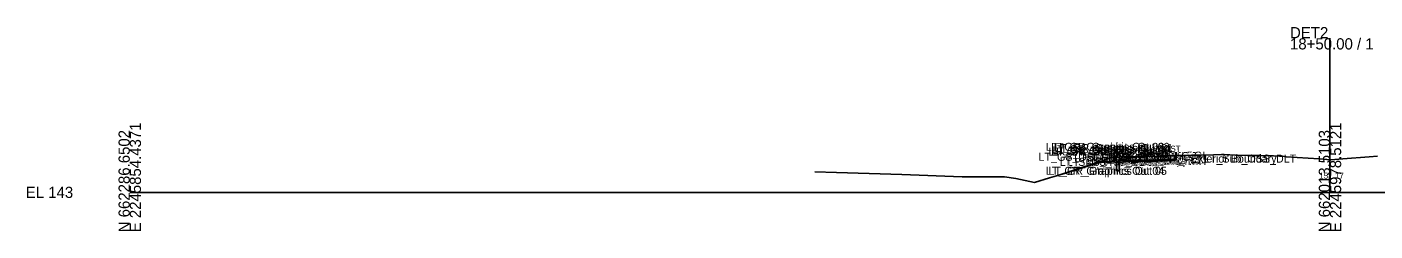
# Model space of a CAD drawing. Extents: x -26 to 603, y -10 to 9526.
# Drawn here: x -25.7 to 311.3, y 1490.3 to 1541.4 of the extents above; entities that cross this region are included whole.
import ezdxf

# ---------------------------------------------------------------- set-up
doc = ezdxf.new("R2010")
doc.units = 0
for name, color, linetype in [('Default', 7, 'Continuous'), ('Exist Cross Section Cell', 7, 'Continuous'), ('Exist XS Center Line Elevation Label', 7, 'Continuous'), ('Exist XS Ground Line', 7, 'Continuous'), ('Prop CMT Guardrail Graphics', 7, 'Continuous'), ('Prop CMT Pvmt Course 1', 7, 'Continuous'), ('Prop CMT Pvmt Course 2', 7, 'Continuous'), ('Prop CMT Pvmt Course 3', 7, 'Continuous'), ('Prop CMT Pvmt Surface', 7, 'Continuous'), ('Prop CMT Pvmt Surface Shoulder', 7, 'Continuous'), ('Prop CMT Shld Paved Course 1', 7, 'Continuous'), ('Prop CMT Shld Paved Course 2', 7, 'Continuous'), ('Prop CMT Shld Paved Course 3', 7, 'Continuous'), ('Prop CMT Slope Grass', 7, 'Continuous'), ('Prop CMT Subgrade Earthwork', 7, 'Continuous'), ('Prop XS SE Text', 7, 'Continuous'), ('Prop XS Side Slope Text', 7, 'Continuous'), ('Scratch_Level_2', 7, 'Continuous')]:
    doc.layers.add(name, color=color, linetype=linetype)

msp = doc.modelspace()

# ---------------------------------------------------------------- linework, layer by layer
at = {"layer": 'Exist Cross Section Cell'}
for p, q in [((300, 1500), (300, 1538.56)), ((0, 1500), (300, 1500)), ((300, 1500), (600, 1500))]:
    msp.add_line(p, q, dxfattribs=at)
at = {"layer": 'Exist XS Ground Line'}
for p, q in [((234.71, 1505.06), (241.84, 1507.32)), ((241.84, 1507.32), (247.92, 1508.19)), ((247.92, 1508.19), (252.23, 1508.88)), ((252.23, 1508.88), (252.65, 1508.89)), ((252.65, 1508.89), (253.46, 1508.92)), ((253.46, 1508.92), (254.75, 1508.96)), ((254.75, 1508.96), (258.62, 1509.11)), ((258.62, 1509.11), (259.31, 1509.2)), ((259.31, 1509.2), (259.85, 1509.19)), ((259.85, 1509.19), (261.29, 1509.19)), ((261.29, 1509.19), (262.49, 1509.23)), ((262.49, 1509.23), (265.41, 1509.28)), ((265.41, 1509.28), (267.33, 1509.31)), ((267.33, 1509.31), (270.91, 1509.36)), ((270.91, 1509.36), (272.92, 1509.44)), ((272.92, 1509.44), (273.57, 1509.49)), ((273.57, 1509.49), (276.4, 1509.3)), ((276.4, 1509.3), (279.42, 1509.24)), ((279.42, 1509.24), (281.12, 1509.21)), ((281.12, 1509.21), (281.89, 1509.19)), ((281.89, 1509.19), (283.67, 1509.16)), ((283.67, 1509.16), (284.44, 1509.19)), ((284.44, 1509.19), (285.91, 1509.15)), ((285.91, 1509.15), (287.38, 1509.09)), ((287.38, 1509.09), (288.15, 1509.07)), ((288.15, 1509.07), (289.04, 1508.88)), ((289.04, 1508.88), (291.81, 1508.72)), ((291.81, 1508.72), (297.3, 1508.4)), ((297.3, 1508.4), (300.23, 1508.15)), ((300.23, 1508.15), (303.23, 1508.38)), ((303.23, 1508.38), (309.76, 1508.87)), ((309.76, 1508.87), (311.89, 1509.04)), ((171.27, 1505.1), (176.66, 1504.94)), ((176.66, 1504.94), (193, 1504.5)), ((193, 1504.5), (208.1, 1503.87)), ((208.1, 1503.87), (218.65, 1503.84)), ((218.65, 1503.84), (221.48, 1503.46)), ((221.48, 1503.46), (226.13, 1502.47)), ((226.13, 1502.47), (229.93, 1503.64)), ((229.93, 1503.64), (231.61, 1504.1)), ((231.61, 1504.1), (234.71, 1505.06))]:
    msp.add_line(p, q, dxfattribs=at)
at = {"layer": 'Prop CMT Guardrail Graphics'}
for points in [[(246.66, 1505.37), (246.66, 1511.37)], [(246.66, 1511.37), (248, 1511.37), (248.27, 1511.08)], [(248.27, 1510.49), (248, 1510.2), (247.33, 1510.2)], [(247.33, 1510.2), (247.33, 1505.37)], [(248.27, 1511.08), (248, 1510.79)], [(248, 1510.79), (248.27, 1510.49)], [(247.33, 1505.37), (246.66, 1505.37)]]:
    msp.add_lwpolyline(points, dxfattribs=at)
at = {"layer": 'Prop CMT Pvmt Course 1'}
for points in [[(261.29, 1509.19), (257.09, 1509.09)], [(257.09, 1509.09), (257.09, 1508.17)], [(257.09, 1508.17), (261.29, 1508.28)], [(261.29, 1508.28), (261.29, 1509.19)]]:
    msp.add_lwpolyline(points, dxfattribs=at)
at = {"layer": 'Prop CMT Pvmt Course 2'}
for points in [[(261.29, 1508.28), (257.09, 1508.17)], [(257.09, 1508.17), (257.09, 1507.84)], [(257.09, 1507.84), (261.29, 1507.94)], [(261.29, 1507.94), (261.29, 1508.28)]]:
    msp.add_lwpolyline(points, dxfattribs=at)
at = {"layer": 'Prop CMT Pvmt Course 3'}
for points in [[(261.29, 1507.94), (257.09, 1507.84)], [(257.09, 1507.84), (261.29, 1507.94)], [(257.09, 1507.84), (257.09, 1507.84)], [(261.29, 1507.94), (261.29, 1507.94)]]:
    msp.add_lwpolyline(points, dxfattribs=at)
at = {"layer": 'Prop CMT Pvmt Surface'}
msp.add_lwpolyline([(261.29, 1509.19), (257.09, 1509.09)], dxfattribs=at)
at = {"layer": 'Prop CMT Pvmt Surface Shoulder'}
msp.add_lwpolyline([(257.09, 1509.09), (248.27, 1508.87)], dxfattribs=at)
at = {"layer": 'Prop CMT Shld Paved Course 1'}
for p, q in [((248.27, 1508.87), (247.33, 1507.93)), ((257.09, 1509.09), (250.03, 1508.91))]:
    msp.add_line(p, q, dxfattribs=at)
for points in [[(249.09, 1507.97), (257.09, 1508.17)], [(257.09, 1508.17), (257.09, 1509.09)]]:
    msp.add_lwpolyline(points, dxfattribs=at)
at = {"layer": 'Prop CMT Shld Paved Course 2'}
for p, q in [((247.33, 1507.93), (247, 1507.6)), ((257.09, 1508.17), (247.33, 1507.93))]:
    msp.add_line(p, q, dxfattribs=at)
for points in [[(248.75, 1507.63), (257.09, 1507.84)], [(257.09, 1507.84), (257.09, 1508.17)]]:
    msp.add_lwpolyline(points, dxfattribs=at)
at = {"layer": 'Prop CMT Shld Paved Course 3'}
for points in [[(257.09, 1507.84), (248.75, 1507.63), (248.25, 1507.62)], [(248.25, 1507.62), (257.09, 1507.84)], [(248.25, 1507.62), (248.25, 1507.62)], [(257.09, 1507.84), (257.09, 1507.84)]]:
    msp.add_lwpolyline(points, dxfattribs=at)
at = {"layer": 'Prop CMT Slope Grass'}
for points in [[(245.27, 1508.63), (232.72, 1504.45)], [(248.27, 1508.87), (245.27, 1508.63)]]:
    msp.add_lwpolyline(points, dxfattribs=at)
at = {"layer": 'Prop CMT Subgrade Earthwork'}
for points in [[(248.25, 1507.62), (241.95, 1507.52)], [(257.09, 1507.84), (248.25, 1507.62)], [(261.29, 1507.94), (257.09, 1507.84)]]:
    msp.add_lwpolyline(points, dxfattribs=at)

# ---------------------------------------------------------------- texts
at = {"layer": 'Default'}
msp.add_text('-', height=0.0001, dxfattribs=at).set_placement((0, 1500))
msp.add_text('-', height=0.0001, dxfattribs=at).set_placement((0, 1500))
msp.add_text('-', height=0.0001, dxfattribs=at).set_placement((0, 1500))
msp.add_text('-', height=0.0001, dxfattribs=at).set_placement((0, 1500))
at = {"layer": 'Exist Cross Section Cell'}
for s, p in [('DET2', (290, 1538.56)), ('18+50.00 / 1', (290, 1535.76)), ('EL 143', (-26, 1498.6))]:
    msp.add_text(s, height=2.8, dxfattribs=at).set_placement(p)
for s, p in [('E 2245854.4371', (2.8, 1490)), ('E 2245978.5121', (302.8, 1490)), ('N 662286.6502', (0, 1490)), ('N 662013.5103', (300, 1490))]:
    msp.add_text(s, height=2.8, rotation=90, dxfattribs=at).set_placement(p)
at = {"layer": 'Exist XS Center Line Elevation Label'}
msp.add_text('151.17', height=1.5, dxfattribs=at).set_placement((297.31, 1503.42))
at = {"layer": 'Prop XS SE Text'}
msp.add_text('EXIST', height=1.5, rotation=1.4321, dxfattribs=at).set_placement((256.89, 1510.08))
at = {"layer": 'Prop XS Side Slope Text'}
msp.add_text('3:1', height=1.5, rotation=18.4332, dxfattribs=at).set_placement((241.28, 1507.95))
at = {"layer": 'Scratch_Level_2'}
for s, p in [('LT_GS_OS_GR_Face_Graphics', (227.16, 1507.89)), ('LT_GR_Graphics Out 03', (228.99, 1510.39)), ('LT_GR_Graphics Out 06', (229.61, 1509.22)), ('LT_GR_Graphics Out 02', (230.33, 1510.39)), ('LT_GR_Graphics Out 09', (230.33, 1509.8)), ('LT_GR_Graphics Out 07', (230.33, 1509.22)), ('LT_GR_Graphics Out 08', (230.6, 1509.51)), ('LT_GR_Graphics Out 01', (231.16, 1510.09)), ('LT_GS_OS_CTL', (236.07, 1507.65)), ('LT_PS1_OEOP', (240.83, 1507.91)), ('LT_PV1_OEOT', (247.83, 1508.09)), ('LT_PV1_PGL', (253.07, 1508.19)), ('Exterior Boundary', (265.25, 1507.45)), ('Exterior Boundary', (265.25, 1507.45)), ('LT_Sub_OSS_DLT', (268.51, 1507.45)), ('LT_Sub_OSS_DLT', (268.51, 1507.45)), ('Exterior Boundary', (227.53, 1506.54)), ('Exterior Boundary', (227.53, 1506.54)), ('LT_GR_Graphics Out 04', (228.99, 1504.39)), ('LT_GR_Graphics Out 05', (229.66, 1504.39)), ('LT_Sub_Trench_Out', (232.45, 1506.62)), ('LT_Slope_Fill', (233.91, 1506.54)), ('LT_Slope_Fill', (233.91, 1506.54)), ('LT_PS3_Shelf_Out', (234.23, 1506.62)), ('LT_PS3_OEOP', (238.98, 1506.63)), ('LT_PS2_OEOP', (239.32, 1506.97)), ('LT_Sub_OEOT', (247.17, 1506.84)), ('LT_PV2_OEOT', (247.26, 1507.17)), ('LT_PV3_OEOT', (247.26, 1506.84)), ('LT_Sub_PGL', (252.4, 1506.94)), ('LT_PV2_PGL', (252.5, 1507.28)), ('LT_PV3_PGL', (252.5, 1506.94))]:
    msp.add_text(s, height=2, dxfattribs=at).set_placement(p)

doc.saveas('drawing.dxf')
